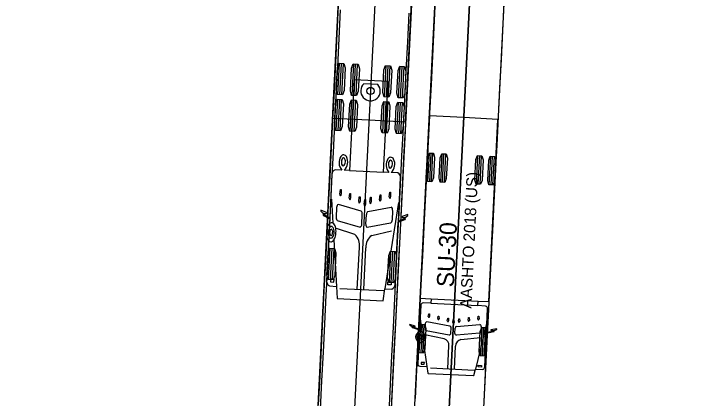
# Model space of a CAD drawing. Extents: x 260275 to 261282, y 610916 to 614143.
# Drawn here: x 260986.2 to 261067.3, y 611927.2 to 611972 of the extents above; entities that cross this region are included whole.
import ezdxf

# ---------------------------------------------------------------- set-up
doc = ezdxf.new("R2010")
doc.units = 0
doc.layers.add('GE_X_Alignment', color=7, linetype='Continuous')
doc.layers.add('UT_X_Water_Cells', color=7, linetype='Continuous')

msp = doc.modelspace()

# ---------------------------------------------------------------- linework, layer by layer
at = {"layer": 'GE_X_Alignment'}
msp.add_line((260986.249, 610915.954), (261148.276, 614142.838), dxfattribs=at)
at = {"layer": 'UT_X_Water_Cells'}
for p, q in [((261044.031, 612066.726), (261023.69, 611661.632)), ((261031.95, 612045.486), (261010.925, 611626.741)), ((261024.011, 611962.561), (261024.195, 611966.223)), ((261024.24, 611962.55), (261024.424, 611966.212)), ((261024.469, 611962.538), (261024.653, 611966.2)), ((261025.659, 611962.479), (261025.843, 611966.141)), ((261025.888, 611962.467), (261026.072, 611966.129)), ((261026.117, 611962.456), (261026.301, 611966.118)), ((261029.438, 611962.289), (261029.622, 611965.951)), ((261029.667, 611962.277), (261029.85, 611965.939)), ((261029.895, 611962.266), (261030.079, 611965.928)), ((261031.086, 611962.206), (261031.269, 611965.868)), ((261031.314, 611962.195), (261031.498, 611965.857)), ((261031.543, 611962.183), (261031.727, 611965.845)), ((261028.656, 611963.76), (261027.042, 611963.841)), ((261023.801, 611958.367), (261023.984, 611962.029)), ((261024.029, 611958.355), (261024.213, 611962.017)), ((261024.258, 611958.344), (261024.442, 611962.006)), ((261025.448, 611958.284), (261025.632, 611961.946)), ((261025.677, 611958.272), (261025.861, 611961.934)), ((261025.906, 611958.261), (261026.09, 611961.923)), ((261029.227, 611958.094), (261029.411, 611961.756)), ((261029.456, 611958.083), (261029.64, 611961.745)), ((261029.685, 611958.071), (261029.869, 611961.733)), ((261030.875, 611958.011), (261031.059, 611961.673)), ((261031.104, 611958), (261031.288, 611961.662)), ((261031.333, 611957.988), (261031.517, 611961.651)), ((261034.495, 611952.414), (261034.662, 611955.743)), ((261034.703, 611952.404), (261034.87, 611955.733)), ((261034.911, 611952.393), (261035.078, 611955.722)), ((261035.993, 611952.339), (261036.16, 611955.668)), ((261036.201, 611952.328), (261036.368, 611955.657)), ((261036.409, 611952.318), (261036.576, 611955.647)), ((261040.154, 611952.13), (261040.321, 611955.459)), ((261040.362, 611952.119), (261040.529, 611955.449)), ((261040.57, 611952.109), (261040.737, 611955.438)), ((261041.652, 611952.055), (261041.819, 611955.384)), ((261041.86, 611952.044), (261042.027, 611955.373)), ((261042.068, 611952.034), (261042.236, 611955.363)), ((261024.467, 611953.761), (261023.692, 611953.8)), ((261025.353, 611953.716), (261029.322, 611953.517)), ((261030.983, 611953.434), (261030.209, 611953.472)), ((261024.24, 611950.946), (261024.303, 611951.493)), ((261024.303, 611951.493), (261024.386, 611951.489)), ((261024.386, 611951.489), (261024.394, 611950.938)), ((261025.336, 611950.504), (261025.4, 611951.052)), ((261025.4, 611951.052), (261025.482, 611951.047)), ((261025.482, 611951.047), (261025.491, 611950.497)), ((261029.998, 611950.657), (261030.061, 611951.204)), ((261030.061, 611951.204), (261030.144, 611951.2)), ((261030.144, 611951.2), (261030.152, 611950.649)), ((261023.27, 611950.378), (261023.423, 611947.578)), ((261026.435, 611950.115), (261026.499, 611950.662)), ((261026.499, 611950.662), (261026.581, 611950.658)), ((261026.581, 611950.658), (261026.59, 611950.107)), ((261027.067, 611949.774), (261027.131, 611950.321)), ((261027.131, 611950.321), (261027.213, 611950.317)), ((261027.213, 611950.317), (261027.222, 611949.766)), ((261027.73, 611950.05), (261027.794, 611950.597)), ((261027.794, 611950.597), (261027.876, 611950.593)), ((261027.876, 611950.593), (261027.884, 611950.042)), ((261028.862, 611950.302), (261028.926, 611950.875)), ((261028.926, 611950.875), (261029.009, 611950.87)), ((261029.009, 611950.87), (261029.017, 611950.295)), ((261023.856, 611949.396), (261023.799, 611948.267)), ((261026.715, 611948.978), (261024.056, 611949.756)), ((261027.493, 611948.938), (261030.216, 611949.447)), ((261031.06, 611949.986), (261029.489, 611939.918)), ((261022.325, 611948.696), (261022.305, 611948.714)), ((261022.35, 611948.696), (261022.325, 611948.696)), ((261026.791, 611947.471), (261026.848, 611948.6)), ((261027.266, 611947.447), (261027.323, 611948.576)), ((261030.379, 611949.068), (261030.322, 611947.939)), ((261023.932, 611947.889), (261026.591, 611947.11)), ((261031.807, 611948.221), (261031.833, 611948.218)), ((261031.833, 611948.218), (261031.854, 611948.234)), ((261025.985, 611946.247), (261023.744, 611946.997)), ((261030.152, 611947.577), (261027.429, 611947.068)), ((261027.945, 611946.149), (261030.238, 611946.668)), ((261022.926, 611945.513), (261022.69, 611940.818)), ((261023.53, 611945.616), (261023.825, 611940.202)), ((261022.928, 611940.989), (261023.112, 611944.651)), ((261023.157, 611940.977), (261023.341, 611944.639)), ((261023.386, 611940.966), (261023.57, 611944.628)), ((261026.263, 611939.854), (261026.509, 611944.74)), ((261027.028, 611939.816), (261027.273, 611944.701)), ((261030.002, 611940.633), (261030.186, 611944.295)), ((261030.231, 611940.622), (261030.415, 611944.284)), ((261030.46, 611940.61), (261030.644, 611944.272)), ((261023.179, 611941.072), (261023.161, 611940.716)), ((261023.161, 611940.716), (261023.539, 611940.697)), ((261023.557, 611941.053), (261023.179, 611941.072)), ((261023.539, 611940.697), (261023.557, 611941.053)), ((261029.823, 611940.382), (261029.841, 611940.737)), ((261029.841, 611940.737), (261030.219, 611940.718)), ((261030.219, 611940.718), (261030.201, 611940.363)), ((261024.229, 611939.957), (261029.328, 611939.701)), ((261030.201, 611940.363), (261029.823, 611940.382)), ((261023.903, 611938.77), (261029.267, 611938.501)), ((261034.829, 611938.228), (261040.314, 611937.952)), ((261034.856, 611938.759), (261040.341, 611938.483)), ((261033.583, 611936.412), (261033.799, 611934.879)), ((261034.539, 611936.701), (261034.589, 611936.998)), ((261034.589, 611936.998), (261034.672, 611936.994)), ((261034.672, 611936.994), (261034.693, 611936.693)), ((261035.644, 611936.435), (261035.695, 611936.732)), ((261035.695, 611936.732), (261035.777, 611936.728)), ((261035.777, 611936.728), (261035.798, 611936.427)), ((261036.75, 611936.197), (261036.801, 611936.494)), ((261036.801, 611936.494), (261036.884, 611936.49)), ((261036.884, 611936.49), (261036.905, 611936.189)), ((261038.045, 611936.131), (261038.096, 611936.429)), ((261038.096, 611936.429), (261038.179, 611936.425)), ((261038.179, 611936.425), (261038.199, 611936.124)), ((261039.17, 611936.244), (261039.221, 611936.555)), ((261039.221, 611936.555), (261039.304, 611936.551)), ((261039.304, 611936.551), (261039.325, 611936.236)), ((261040.297, 611936.412), (261040.347, 611936.709)), ((261040.347, 611936.709), (261040.43, 611936.705)), ((261040.43, 611936.705), (261040.451, 611936.404)), ((261033.492, 611932.439), (261033.659, 611935.768)), ((261033.7, 611932.429), (261033.867, 611935.758)), ((261033.908, 611932.418), (261034.075, 611935.747)), ((261034.19, 611935.862), (261034.16, 611935.246)), ((261037.055, 611935.569), (261034.382, 611936.055)), ((261037.389, 611935.996), (261037.44, 611936.294)), ((261037.44, 611936.294), (261037.523, 611936.289)), ((261037.523, 611936.289), (261037.544, 611935.988)), ((261037.833, 611935.53), (261040.542, 611935.746)), ((261041.373, 611936.021), (261040.032, 611930.554)), ((261034.301, 611935.037), (261036.974, 611934.551)), ((261037.166, 611934.743), (261037.197, 611935.359)), ((261037.641, 611934.719), (261037.672, 611935.335)), ((261040.649, 611932.08), (261040.816, 611935.409)), ((261040.713, 611935.535), (261040.682, 611934.919)), ((261040.857, 611932.069), (261041.025, 611935.398)), ((261041.065, 611932.059), (261041.233, 611935.388)), ((261036.388, 611934.093), (261034.133, 611934.554)), ((261040.521, 611934.725), (261037.812, 611934.509)), ((261038.349, 611933.995), (261040.627, 611934.226)), ((261033.447, 611933.713), (261033.321, 611931.194)), ((261033.951, 611933.804), (261034.369, 611930.838)), ((261036.812, 611930.592), (261036.946, 611933.257)), ((261037.577, 611930.554), (261037.711, 611933.219)), ((261033.703, 611931.328), (261033.694, 611931.134)), ((261033.694, 611931.134), (261034.072, 611931.115)), ((261034.082, 611931.309), (261033.703, 611931.328)), ((261034.072, 611931.115), (261034.082, 611931.309)), ((261040.356, 611930.799), (261040.365, 611930.993)), ((261040.734, 611930.78), (261040.356, 611930.799)), ((261040.365, 611930.993), (261040.743, 611930.974)), ((261040.743, 611930.974), (261040.734, 611930.78)), ((261034.778, 611930.694), (261039.876, 611930.438))]:
    msp.add_line(p, q, dxfattribs=at)
for points in [[(261009.34, 611680.102), (261030.965, 612110.617), (261039.455, 612110.191), (261039.447, 612110.045), (261039.447, 612110.045)], [(261039.447, 612110.045), (261018.12, 611685.301)], [(261020.965, 611687.133), (261041.34, 612092.893), (261049.33, 612092.492), (261049.322, 612092.345), (261049.322, 612092.345)], [(261049.322, 612092.345), (261028.546, 611678.469)], [(261025.82, 612007.69), (261025.797, 612007.691), (261023.394, 611959.822), (261027.638, 611959.609), (261031.883, 611959.396), (261034.287, 612007.265), (261034.264, 612007.266)], [(261035.356, 611973.728), (261035.189, 611970.399), (261035.022, 611967.071), (261034.855, 611963.742), (261034.688, 611960.413), (261034.521, 611957.085), (261034.353, 611953.756), (261034.186, 611950.428), (261034.019, 611947.099), (261033.852, 611943.77), (261033.685, 611940.442), (261033.518, 611937.113), (261033.351, 611933.784), (261033.183, 611930.456), (261033.016, 611927.127)], [(261035.356, 611973.725), (261035.189, 611970.396), (261035.022, 611967.068), (261034.855, 611963.739), (261034.688, 611960.41), (261034.52, 611957.082), (261034.353, 611953.753), (261034.186, 611950.424), (261034.019, 611947.096), (261033.852, 611943.767), (261033.685, 611940.439), (261033.518, 611937.11), (261033.35, 611933.781), (261033.183, 611930.453), (261033.016, 611927.124)], [(261024.054, 611972.977), (261023.887, 611969.648), (261023.72, 611966.319), (261023.553, 611962.991), (261023.386, 611959.662), (261023.219, 611956.333), (261023.052, 611953.005), (261022.884, 611949.676), (261022.717, 611946.348), (261022.55, 611943.019), (261022.383, 611939.69), (261022.216, 611936.362), (261022.049, 611933.033), (261021.882, 611929.704), (261021.714, 611926.376)], [(261043.346, 611973.327), (261043.179, 611969.998), (261043.012, 611966.669), (261042.845, 611963.341), (261042.678, 611960.012), (261042.51, 611956.684), (261042.343, 611953.355), (261042.176, 611950.026), (261042.009, 611946.698), (261041.842, 611943.369), (261041.675, 611940.04), (261041.508, 611936.712), (261041.341, 611933.383), (261041.173, 611930.055), (261041.006, 611926.726)], [(261043.346, 611973.324), (261043.179, 611969.995), (261043.012, 611966.666), (261042.845, 611963.338), (261042.677, 611960.009), (261042.51, 611956.68), (261042.343, 611953.352), (261042.176, 611950.023), (261042.009, 611946.695), (261041.842, 611943.366), (261041.675, 611940.037), (261041.508, 611936.709), (261041.34, 611933.38), (261041.173, 611930.051), (261041.006, 611926.723)], [(261024.279, 611972.456), (261024.111, 611969.127), (261023.944, 611965.799), (261023.777, 611962.47), (261023.61, 611959.141), (261023.443, 611955.813), (261023.276, 611952.484), (261023.109, 611949.155), (261022.941, 611945.827), (261022.774, 611942.498), (261022.607, 611939.17), (261022.44, 611935.841), (261022.273, 611932.512), (261022.106, 611929.184), (261021.939, 611925.855)], [(261032.268, 611972.055), (261032.101, 611968.726), (261031.934, 611965.398), (261031.767, 611962.069), (261031.6, 611958.74), (261031.433, 611955.412), (261031.266, 611952.083), (261031.098, 611948.754), (261030.931, 611945.426), (261030.764, 611942.097), (261030.597, 611938.768), (261030.43, 611935.44), (261030.263, 611932.111), (261030.096, 611928.782), (261029.929, 611925.454)], [(261032.544, 611972.55), (261032.376, 611969.222), (261032.209, 611965.893), (261032.042, 611962.565), (261031.875, 611959.236), (261031.708, 611955.907), (261031.541, 611952.579), (261031.374, 611949.25), (261031.207, 611945.921), (261031.039, 611942.593), (261030.872, 611939.264), (261030.705, 611935.935), (261030.538, 611932.607), (261030.371, 611929.278), (261030.204, 611925.949)], [(261029.952, 611953.485), (261029.322, 611953.517), (261029.854, 611964.104), (261025.885, 611964.303), (261025.353, 611953.716), (261024.724, 611953.748)], [(261041.212, 611937.907), (261040.318, 611937.952), (261040.315, 611937.956), (261040.341, 611938.482), (261040.352, 611938.483), (261041.593, 611938.421), (261042.661, 611959.68), (261038.666, 611959.881), (261034.671, 611960.082), (261033.604, 611938.822), (261034.845, 611938.759), (261034.856, 611938.758), (261034.83, 611938.232), (261034.826, 611938.228), (261033.931, 611938.273)], [(261023.315, 611953.26), (261023.06, 611948.185), (261022.357, 611948.576), (261022.356, 611948.577)], [(261031.789, 611948.103), (261031.789, 611948.103), (261031.05, 611947.784), (261031.305, 611952.859)], [(261022.347, 611948.614), (261022.35, 611948.696), (261022.671, 611948.696), (261022.676, 611948.799), (261022.028, 611949.089), (261022.022, 611948.969), (261022.305, 611948.714), (261022.301, 611948.626)], [(261031.849, 611948.147), (261031.854, 611948.234), (261032.161, 611948.46), (261032.167, 611948.58), (261031.493, 611948.356), (261031.488, 611948.253), (261031.807, 611948.221), (261031.802, 611948.139)], [(261022.335, 611948.491), (261023.055, 611948.085), (261023.026, 611947.513)], [(261030.68, 611940.417), (261031.045, 611947.684), (261031.801, 611948.016)], [(261023.011, 611940.243), (261023.825, 611940.202), (261023.903, 611938.782)], [(261023.903, 611938.77), (261029.267, 611938.501), (261029.489, 611939.918), (261030.302, 611939.877)], [(261033.661, 611937.971), (261033.522, 611935.2), (261033.516, 611935.188), (261032.711, 611935.449), (261032.711, 611935.449)], [(261042.144, 611934.975), (261042.143, 611934.975), (261041.316, 611934.797), (261041.312, 611934.809), (261041.451, 611937.58)], [(261032.701, 611935.469), (261032.702, 611935.514), (261032.703, 611935.514), (261033.02, 611935.507), (261033.023, 611935.507), (261033.026, 611935.562), (261033.023, 611935.564), (261032.375, 611935.736), (261032.372, 611935.736), (261032.368, 611935.671), (261032.656, 611935.525), (261032.657, 611935.524), (261032.655, 611935.477)], [(261032.692, 611935.402), (261032.693, 611935.402), (261033.512, 611935.134), (261033.518, 611935.122), (261033.506, 611934.894)], [(261041.111, 611930.803), (261041.308, 611934.731), (261041.315, 611934.742), (261042.157, 611934.927), (261042.158, 611934.927)], [(261042.202, 611934.998), (261042.205, 611935.045), (261042.206, 611935.045), (261042.507, 611935.162), (261042.51, 611935.227), (261042.507, 611935.227), (261041.845, 611935.121), (261041.842, 611935.12), (261041.839, 611935.064), (261041.842, 611935.064), (261042.158, 611935.039), (261042.159, 611935.039), (261042.156, 611934.995)], [(261033.559, 611930.879), (261034.365, 611930.838), (261034.37, 611930.833), (261034.479, 611930.055), (261034.521, 611930.051), (261037.162, 611929.919), (261039.802, 611929.786), (261039.844, 611929.786), (261040.031, 611930.549), (261040.036, 611930.553), (261040.842, 611930.513)]]:
    msp.add_lwpolyline(points, dxfattribs=at)
for points in [[(261024.526, 611962.536), (261023.954, 611962.564), (261023.808, 611963.086), (261023.94, 611965.722), (261024.138, 611966.226), (261024.71, 611966.198), (261024.856, 611965.676), (261024.724, 611963.04)], [(261026.174, 611962.453), (261025.602, 611962.481), (261025.456, 611963.003), (261025.588, 611965.639), (261025.786, 611966.144), (261026.357, 611966.115), (261026.504, 611965.594), (261026.371, 611962.957)], [(261029.952, 611962.263), (261029.381, 611962.292), (261029.234, 611962.813), (261029.367, 611965.45), (261029.565, 611965.954), (261030.136, 611965.925), (261030.282, 611965.404), (261030.15, 611962.767)], [(261031.6, 611962.18), (261031.029, 611962.209), (261030.882, 611962.73), (261031.015, 611965.367), (261031.213, 611965.871), (261031.784, 611965.842), (261031.93, 611965.321), (261031.798, 611962.684)], [(261024.315, 611958.341), (261023.744, 611958.369), (261023.597, 611958.891), (261023.73, 611961.528), (261023.928, 611962.032), (261024.499, 611962.003), (261024.645, 611961.482), (261024.513, 611958.845)], [(261025.963, 611958.258), (261025.392, 611958.287), (261025.245, 611958.808), (261025.378, 611961.445), (261025.576, 611961.949), (261026.147, 611961.92), (261026.293, 611961.399), (261026.161, 611958.762)], [(261029.742, 611958.068), (261029.17, 611958.097), (261029.024, 611958.618), (261029.156, 611961.255), (261029.354, 611961.759), (261029.925, 611961.73), (261030.072, 611961.209), (261029.939, 611958.572)], [(261031.389, 611957.986), (261030.818, 611958.014), (261030.672, 611958.536), (261030.804, 611961.172), (261031.002, 611961.676), (261031.573, 611961.648), (261031.72, 611961.126), (261031.587, 611958.49)], [(261034.962, 611952.391), (261034.443, 611952.417), (261034.31, 611952.891), (261034.43, 611955.287), (261034.61, 611955.746), (261035.13, 611955.72), (261035.263, 611955.246), (261035.142, 611952.849)], [(261036.46, 611952.315), (261035.941, 611952.341), (261035.808, 611952.815), (261035.928, 611955.212), (261036.108, 611955.67), (261036.628, 611955.644), (261036.761, 611955.17), (261036.64, 611952.774)], [(261040.622, 611952.106), (261040.103, 611952.132), (261039.969, 611952.606), (261040.09, 611955.003), (261040.27, 611955.462), (261040.789, 611955.435), (261040.922, 611954.962), (261040.802, 611952.565)], [(261042.12, 611952.031), (261041.601, 611952.057), (261041.468, 611952.531), (261041.588, 611954.928), (261041.768, 611955.386), (261042.287, 611955.36), (261042.42, 611954.886), (261042.3, 611952.489)], [(261023.442, 611940.963), (261022.871, 611940.991), (261022.725, 611941.513), (261022.857, 611944.149), (261023.055, 611944.653), (261023.626, 611944.625), (261023.773, 611944.103), (261023.64, 611941.467)], [(261030.517, 611940.607), (261029.946, 611940.636), (261029.799, 611941.158), (261029.932, 611943.794), (261030.129, 611944.298), (261030.701, 611944.27), (261030.847, 611943.748), (261030.715, 611941.112)], [(261033.959, 611932.416), (261033.44, 611932.442), (261033.307, 611932.916), (261033.427, 611935.313), (261033.607, 611935.771), (261034.127, 611935.745), (261034.26, 611935.271), (261034.139, 611932.874)], [(261041.117, 611932.056), (261040.598, 611932.082), (261040.465, 611932.556), (261040.585, 611934.953), (261040.765, 611935.411), (261041.284, 611935.385), (261041.417, 611934.911), (261041.297, 611932.514)]]:
    msp.add_lwpolyline(points, close=True, dxfattribs=at)
for centre, radius in [((261027.808, 611962.993), 0.424), ((261033.622, 611934.296), 0.374), ((261033.622, 611934.296), 0.193)]:
    msp.add_circle(centre, radius, dxfattribs=at)
for centre, radius, start, end in [((261027.808, 611962.993), 1.143, 132.1255, 42.1255), ((261025.479, 611954.644), 1.344, 147.53526, 221.09006), ((261024.665, 611955.155), 0.383, 27.59628, 146.65472), ((261025.268, 611954.694), 0.86, 155.59014, 195.55953), ((261024.699, 611954.971), 0.228, 97.92836, 159.8232), ((261024.592, 611954.946), 0.262, 6.80834, 73.33353), ((261023.805, 611954.728), 1.344, 313.16094, 26.71574), ((261030.964, 611954.368), 1.344, 147.53526, 221.09006), ((261030.15, 611954.871), 0.387, 28.62104, 145.62996), ((261029.29, 611954.453), 1.344, 313.16094, 26.71574), ((261024.722, 611954.531), 0.29, 193.32121, 249.48124), ((261024.582, 611954.503), 0.247, 278.8428, 348.7219), ((261024, 611954.76), 0.879, 339.66236, 14.25761), ((261030.772, 611954.42), 0.879, 159.9934, 194.58864), ((261030.202, 611954.664), 0.262, 100.91747, 167.44267), ((261030.099, 611954.7), 0.228, 14.4278, 76.32264), ((261029.505, 611954.482), 0.86, 338.69148, 18.66086), ((261023.886, 611953.262), 0.571, 109.81853, 180.21012), ((261030.168, 611954.223), 0.247, 185.52911, 255.4082), ((261030.032, 611954.264), 0.29, 284.76976, 340.92979), ((261030.736, 611952.918), 0.571, 354.04089, 64.43248), ((261024.425, 611950.895), 0.192, 164.57524, 232.04981), ((261024.205, 611950.906), 0.192, 302.17384, 9.70311), ((261025.522, 611950.453), 0.192, 164.57524, 232.04981), ((261025.301, 611950.464), 0.192, 302.17384, 9.70311), ((261029.048, 611950.276), 0.192, 164.5479, 232.07716), ((261028.827, 611950.287), 0.192, 302.20119, 9.67576), ((261030.183, 611950.605), 0.192, 164.5479, 232.07716), ((261029.963, 611950.617), 0.192, 302.20119, 9.67576), ((261024.189, 611949.45), 0.334, 113.39037, 185.98833), ((261026.621, 611950.063), 0.192, 164.57524, 232.04981), ((261026.4, 611950.074), 0.192, 302.17384, 9.70311), ((261027.253, 611949.723), 0.192, 164.57524, 232.04981), ((261027.032, 611949.734), 0.192, 302.20119, 9.67576), ((261027.915, 611949.998), 0.192, 164.5479, 232.07716), ((261027.695, 611950.01), 0.192, 302.20119, 9.67576), ((261030.053, 611949.156), 0.334, 348.26267, 60.86063), ((261022.406, 611948.553), 0.127, 145.02093, 209.23008), ((261022.246, 611948.569), 0.11, 4.06966, 24.17798), ((261026.456, 611948.676), 0.397, 351.20134, 49.36435), ((261027.72, 611948.613), 0.397, 124.88665, 183.04966), ((261022.315, 611948.505), 0.0244, 212.94354, 326.25791), ((261024.196, 611948.194), 0.403, 169.66784, 229.12579), ((261029.92, 611947.907), 0.403, 305.12521, 4.58316), ((261031.898, 611948.084), 0.11, 150.07302, 170.18134), ((261031.823, 611948.027), 0.0244, 207.99309, 321.30746), ((261031.738, 611948.085), 0.127, 325.02093, 29.23008), ((261024.862, 611946.419), 2.204, 164.32456, 183.95974), ((261023.645, 611946.827), 0.924, 132.02262, 168.30076), ((261023.791, 611946.533), 0.913, 140.43513, 180.69541), ((261023.261, 611947.325), 0.301, 57.35677, 141.25506), ((261023.243, 611946.991), 0.199, 40.92879, 141.5681), ((261022.654, 611946.583), 0.914, 353.95993, 36.01791), ((261022.933, 611946.947), 0.799, 12.92493, 52.19257), ((261021.773, 611946.59), 2.012, 356.76687, 15.44978), ((261026.45, 611947.418), 0.342, 295.59721, 5.52369), ((261027.6, 611947.36), 0.342, 168.72731, 238.65379), ((261024.391, 611946.372), 1.731, 183.5106, 198.70836), ((261024.111, 611946.452), 1.234, 176.75519, 194.33734), ((261023.318, 611946.205), 0.407, 188.35614, 251.16055), ((261023.675, 611946.476), 0.631, 150.93378, 193.73431), ((261023.279, 611946.358), 0.22, 188.13535, 249.83363), ((261023.234, 611946.737), 0.12, 12.10162, 157.57965), ((261023.119, 611946.407), 0.27, 288.27444, 1.01824), ((261022.782, 611946.525), 0.617, 349.4131, 22.60389), ((261022.466, 611946.52), 1.098, 330.39127, 358.28386), ((261021.734, 611946.568), 2.049, 341.50654, 357.43184), ((261024.903, 611945.027), 1.631, 349.85894, 48.44967), ((261028.899, 611944.826), 1.631, 125.80134, 184.39207), ((261023.443, 611946.011), 0.719, 195.6559, 223.91288), ((261023.187, 611945.711), 0.328, 217.21385, 266.11819), ((261023.162, 611945.764), 0.38, 270.45588, 320.97941), ((261023.176, 611946.087), 0.268, 272.19814, 335.87577), ((261022.652, 611946.235), 1.074, 318.58211, 342.85096), ((261023.479, 611940.882), 0.792, 184.65895, 233.81442), ((261029.901, 611940.56), 0.792, 300.43659, 349.59206), ((261033.983, 611937.954), 0.323, 99.2771, 177.1255), ((261041.129, 611937.596), 0.323, 357.1255, 74.97391), ((261034.627, 611936.678), 0.091, 165.44206, 259.60593), ((261034.603, 611936.679), 0.0909, 274.60942, 8.84462), ((261035.732, 611936.412), 0.091, 165.44206, 259.60593), ((261035.708, 611936.413), 0.0909, 274.60942, 8.84462), ((261040.385, 611936.389), 0.0909, 165.40639, 259.64159), ((261040.361, 611936.39), 0.091, 274.64508, 8.80895), ((261034.375, 611935.871), 0.184, 87.71808, 182.58934), ((261036.838, 611936.174), 0.091, 165.44206, 259.60593), ((261036.815, 611936.175), 0.0909, 274.60942, 8.84462), ((261037.477, 611935.973), 0.091, 165.44206, 259.60593), ((261037.454, 611935.974), 0.091, 274.64508, 8.80895), ((261038.133, 611936.109), 0.0909, 165.40639, 259.64159), ((261038.11, 611936.11), 0.091, 274.64508, 8.80895), ((261039.258, 611936.235), 0.0909, 165.40639, 259.64159), ((261039.234, 611936.236), 0.091, 274.64508, 8.80895), ((261040.531, 611935.562), 0.184, 351.66167, 86.53293), ((261032.674, 611935.44), 0.0418, 117.61865, 294.63358), ((261032.668, 611935.44), 0.0434, 11.03902, 41.7118), ((261033.689, 611934.293), 0.628, 106.8788, 247.3705), ((261033.626, 611934.383), 0.524, 49.38452, 103.18459), ((261033.553, 611934.307), 0.63, 356.4803, 48.88311), ((261034.351, 611935.223), 0.193, 173.06859, 254.98308), ((261037.005, 611935.383), 0.193, 353.06366, 74.98801), ((261037.864, 611935.339), 0.193, 99.26299, 181.18734), ((261040.489, 611934.915), 0.193, 279.26792, 1.18241), ((261042.185, 611934.963), 0.0434, 132.53921, 163.21198), ((261042.179, 611934.963), 0.0418, 239.61742, 56.63235), ((261033.553, 611934.292), 0.629, 309.17109, 357.86038), ((261036.178, 611933.349), 0.773, 353.15088, 74.23504), ((261036.981, 611934.735), 0.184, 267.72364, 2.58377), ((261037.823, 611934.693), 0.184, 171.66723, 266.52737), ((261038.483, 611933.233), 0.773, 100.01597, 181.10013), ((261033.618, 611934.21), 0.526, 251.07067, 309.31667), ((261033.6, 611931.157), 0.282, 172.49767, 261.5771), ((261040.829, 611930.794), 0.282, 272.67391, 1.75333)]:
    msp.add_arc(centre, radius, start, end, dxfattribs=at)
for centre, major_axis, start_param, end_param in [((261022.318, 611948.558), (-0.0039, -0.0781), 2.398717, 3.668019), ((261022.318, 611948.558), (0.0039, 0.0781), 3.71124, 4.981984), ((261031.826, 611948.08), (-0.0039, -0.0781), 4.442794, 5.713538), ((261031.826, 611948.08), (0.0039, 0.0781), 5.756759, 7.026061)]:
    msp.add_ellipse(centre, major_axis=major_axis, ratio=0.5, start_param=start_param, end_param=end_param, dxfattribs=at)

# ---------------------------------------------------------------- texts
for s, height, p in [('AASHTO 2018 (US)', 1.33333, (261039.556, 611937.594)), ('SU-30', 2, (261037.51, 611940.057))]:
    msp.add_text(s, height=height, rotation=87.1255, dxfattribs=at).set_placement(p)

doc.saveas('drawing.dxf')
